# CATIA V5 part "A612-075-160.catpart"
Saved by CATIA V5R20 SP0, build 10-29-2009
Part number: A612-075-160
Source: Unknown
Property "A": "25.000"
Property "ARTICLENO": "A612-075-160"
Property "B": "35.000"
Property "BOMINFO": "A612-075-160"
Property "CODE": "A612-075-160"
Property "D": "17.500"
Property "FORM": "A"
Property "L": "160.000"
Property "L1": "45.000"
Property "L2": "70.000"
Property "L3": "0.000"
Property "LINA": "A612-075-160"
Property "NB": "A612-075-160"
Property "NBSYN": "$CODE."
Property "NN": "A612"
Property "NT": "CDI 3357 E-Type Wear Plates, steel and self-lubricating"
Property "SUPPLIER": "CF"
Property "T": "25.000"
Property "W": "75.000"
Bounding box of the stored display mesh (mm): x 0 to 25, y 0 to 160, z 0 to 75
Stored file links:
  C:\Users\Utente\Desktop\3D files A612\A612-075-160.catpart
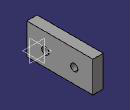
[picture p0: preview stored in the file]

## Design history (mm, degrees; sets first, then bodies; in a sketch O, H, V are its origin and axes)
Body1 "Geometry.1" (main body)
  Solid1 "A612-075-160.catpart": solid without history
